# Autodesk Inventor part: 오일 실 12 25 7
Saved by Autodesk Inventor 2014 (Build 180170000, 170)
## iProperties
Created: 2026-08
Part Number: 오일 실 12 25 7
Material: 일반
Document SubType Name: Modeling
Designer: dg
Density: 1 g/cm^3
Appearance: 기본값
Author: dg
Author: jhkim
Description: 오일-실
Creation Date: 2026-07-31
Sending System: Autodesk Inventor 2027
Preprocessor: ST-DEVELOPER v20.1
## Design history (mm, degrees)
node "오일 실 12 25 71"
body "Solid1"
node "기준1"
